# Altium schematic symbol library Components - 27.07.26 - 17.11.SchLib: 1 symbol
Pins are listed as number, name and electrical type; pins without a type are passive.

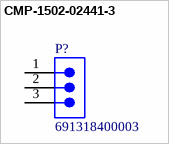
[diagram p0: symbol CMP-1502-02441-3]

## CMP-1502-02441-3
designator P?, comment 691318400003
Terminal Block, 7.62MM Pitch, Close Vertical Pcb Header, Flanges, 3 Pins
footprint 691318400003 (7.62 mm - Closed Vertical PCB Header with Flanges - 3p)
pins: 1, 2, 3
